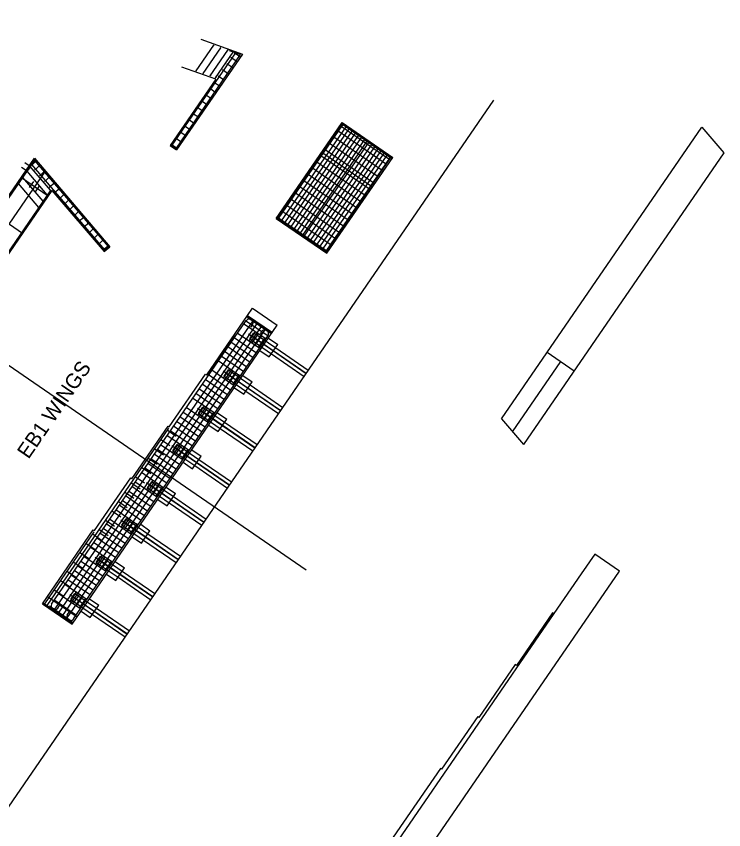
# Model space of a CAD drawing. Extents: x 2378999 to 2381348, y 331302 to 333122.
# Drawn here: x 2379415.6 to 2379509.6, y 331652.7 to 331760.8 of the extents above; entities that cross this region are included whole.
import ezdxf

# ---------------------------------------------------------------- set-up
doc = ezdxf.new("R2010")
doc.units = 0
for name, color, linetype in [('Arrowhead Terminators', 7, 'Continuous'), ('Dimension Lines', 7, 'Continuous'), ('Dimension Lines CELL', 7, 'Continuous'), ('Mis Work Point CELL', 7, 'Continuous'), ('P_SMU_Girder_Concrete', 7, 'Continuous'), ('P_SMU_Rebar_B_Bar', 7, 'Continuous'), ('P_SMU_Rebar_H_Bar', 7, 'Continuous'), ('P_SMU_Rebar_U_Bar', 7, 'Continuous'), ('P_SMU_Rebar_V_Bar', 7, 'Continuous'), ('Rebar Lines', 7, 'Continuous'), ('Scratch_Level_0', 7, 'Continuous'), ('Sup Concrete Slab Lines', 7, 'Continuous'), ('Text', 7, 'Continuous')]:
    doc.layers.add(name, color=color, linetype=linetype)

msp = doc.modelspace()

# ---------------------------------------------------------------- linework, layer by layer
at = {"layer": 'Arrowhead Terminators'}
for p, q in [((2379420.33, 331682.71), (2379446.2, 331720.36)), ((2379420.67, 331681.88), (2379447.1, 331720.34)), ((2379421.22, 331681.5), (2379447.65, 331719.97)), ((2379421.77, 331681.13), (2379448.2, 331719.59)), ((2379447.01, 331719.81), (2379446.77, 331719.47)), ((2379422.32, 331680.75), (2379448.75, 331719.21)), ((2379448.28, 331718.94), (2379448.04, 331718.59)), ((2379423.22, 331680.73), (2379449.09, 331718.38)), ((2379419.73, 331682.53), (2379435.92, 331706.08)), ((2379419.41, 331682.75), (2379425.97, 331692.29)), ((2379421.14, 331682.15), (2379421.37, 331682.5)), ((2379422.41, 331681.28), (2379422.64, 331681.62))]:
    msp.add_line(p, q, dxfattribs=at)
for centre, start, end in [((2379446.61, 331720.09), 325.5093, 145.5093), ((2379448.68, 331718.66), 325.5093, 145.5093), ((2379420.73, 331682.43), 145.5093, 325.5093), ((2379422.81, 331681), 145.5093, 325.5093)]:
    msp.add_arc(centre, 0.49, start, end, dxfattribs=at)
at = {"layer": 'Dimension Lines'}
for p, q in [((2379443.75, 331756.27), (2379443.8, 331756.43)), ((2379444.46, 331756.02), (2379444.51, 331756.18)), ((2379417.48, 331740.82), (2379416.76, 331741.31)), ((2379417.06, 331740.2), (2379416.34, 331740.69)), ((2379446.38, 331720.78), (2379449.37, 331718.72)), ((2379445.84, 331719.99), (2379448.83, 331717.94)), ((2379446.11, 331720.38), (2379449.1, 331718.33)), ((2379444.99, 331718.75), (2379447.98, 331716.7)), ((2379446.53, 331717.6), (2379447.47, 331718.97)), ((2379446.94, 331717.32), (2379447.88, 331718.69)), ((2379444.14, 331717.52), (2379447.13, 331715.46)), ((2379444.57, 331718.13), (2379447.56, 331716.08)), ((2379447.35, 331717.03), (2379448.29, 331718.41)), ((2379447.76, 331716.75), (2379448.71, 331718.12)), ((2379443.29, 331716.28), (2379446.28, 331714.23)), ((2379443.72, 331716.9), (2379446.71, 331714.85)), ((2379442.87, 331715.66), (2379445.86, 331713.61)), ((2379442.45, 331715.04), (2379445.43, 331712.99)), ((2379441.17, 331713.19), (2379444.16, 331711.14)), ((2379441.6, 331713.81), (2379444.58, 331711.75)), ((2379443.13, 331712.65), (2379444.07, 331714.03)), ((2379443.54, 331712.37), (2379444.48, 331713.74)), ((2379443.95, 331712.09), (2379444.9, 331713.46)), ((2379444.37, 331711.8), (2379445.31, 331713.18)), ((2379440.32, 331711.95), (2379443.31, 331709.9)), ((2379440.75, 331712.57), (2379443.73, 331710.52)), ((2379439.9, 331711.33), (2379442.89, 331709.28)), ((2379439.05, 331710.1), (2379442.04, 331708.05)), ((2379439.47, 331710.72), (2379442.46, 331708.66)), ((2379438.2, 331708.86), (2379441.19, 331706.81)), ((2379439.73, 331707.71), (2379440.67, 331709.08)), ((2379440.14, 331707.42), (2379441.09, 331708.8)), ((2379437.35, 331707.63), (2379440.34, 331705.57)), ((2379437.77, 331708.24), (2379440.76, 331706.19)), ((2379440.56, 331707.14), (2379441.5, 331708.52)), ((2379440.97, 331706.86), (2379441.91, 331708.23)), ((2379436.92, 331707.01), (2379439.91, 331704.95)), ((2379436.07, 331705.77), (2379439.06, 331703.72)), ((2379436.5, 331706.39), (2379439.49, 331704.34)), ((2379435.65, 331705.15), (2379438.64, 331703.1)), ((2379434.38, 331703.3), (2379437.36, 331701.25)), ((2379434.8, 331703.92), (2379437.79, 331701.86)), ((2379436.33, 331702.76), (2379437.28, 331704.14)), ((2379436.75, 331702.48), (2379437.69, 331703.85)), ((2379437.16, 331702.2), (2379438.1, 331703.57)), ((2379433.95, 331702.68), (2379436.94, 331700.63)), ((2379437.57, 331701.91), (2379438.51, 331703.29)), ((2379433.1, 331701.44), (2379436.09, 331699.39)), ((2379433.53, 331702.06), (2379436.51, 331700.01)), ((2379432.25, 331700.21), (2379435.24, 331698.16)), ((2379432.68, 331700.83), (2379435.67, 331698.77)), ((2379431.4, 331698.97), (2379434.39, 331696.92)), ((2379432.94, 331697.82), (2379433.88, 331699.19)), ((2379430.98, 331698.35), (2379433.97, 331696.3)), ((2379433.35, 331697.53), (2379434.29, 331698.91)), ((2379433.76, 331697.25), (2379434.7, 331698.62)), ((2379434.17, 331696.97), (2379435.12, 331698.34)), ((2379430.13, 331697.12), (2379433.12, 331695.06)), ((2379430.55, 331697.74), (2379433.54, 331695.68)), ((2379429.28, 331695.88), (2379432.27, 331693.83)), ((2379429.7, 331696.5), (2379432.69, 331694.45)), ((2379428.86, 331695.26), (2379431.84, 331693.21)), ((2379428.01, 331694.03), (2379430.99, 331691.97)), ((2379429.54, 331692.87), (2379430.48, 331694.25)), ((2379429.95, 331692.59), (2379430.89, 331693.96)), ((2379430.36, 331692.31), (2379431.31, 331693.68)), ((2379427.16, 331692.79), (2379430.14, 331690.74)), ((2379427.58, 331693.41), (2379430.57, 331691.36)), ((2379430.77, 331692.02), (2379431.72, 331693.4)), ((2379426.31, 331691.55), (2379429.29, 331689.5)), ((2379426.73, 331692.17), (2379429.72, 331690.12)), ((2379425.88, 331690.94), (2379428.87, 331688.88)), ((2379425.46, 331690.32), (2379428.45, 331688.26)), ((2379426.14, 331687.93), (2379427.08, 331689.3)), ((2379424.18, 331688.46), (2379427.17, 331686.41)), ((2379424.61, 331689.08), (2379427.6, 331687.03)), ((2379426.55, 331687.64), (2379427.5, 331689.02)), ((2379426.96, 331687.36), (2379427.91, 331688.73)), ((2379427.38, 331687.08), (2379428.32, 331688.45)), ((2379423.33, 331687.23), (2379426.32, 331685.17)), ((2379423.76, 331687.84), (2379426.75, 331685.79)), ((2379422.91, 331686.61), (2379425.9, 331684.56)), ((2379422.06, 331685.37), (2379425.05, 331683.32)), ((2379422.48, 331685.99), (2379425.47, 331683.94)), ((2379421.21, 331684.14), (2379424.2, 331682.08)), ((2379422.74, 331682.98), (2379423.69, 331684.36)), ((2379423.16, 331682.7), (2379424.1, 331684.07)), ((2379420.64, 331683.3), (2379423.62, 331681.25)), ((2379423.57, 331682.42), (2379424.51, 331683.79)), ((2379423.98, 331682.13), (2379424.92, 331683.51)), ((2379420.06, 331682.46), (2379423.05, 331680.41))]:
    msp.add_line(p, q, dxfattribs=at)
at = {"layer": 'Dimension Lines CELL'}
msp.add_line((2379454.16, 331687.23), (2379268.2, 331815), dxfattribs=at)
at = {"layer": 'Mis Work Point CELL'}
for p, q in [((2379402.05, 331637.52), (2379479.08, 331749.64)), ((2379392.88, 331701.47), (2379419.5, 331740.21))]:
    msp.add_line(p, q, dxfattribs=at)
at = {"layer": 'P_SMU_Girder_Concrete'}
for p, q in [((2379417.39, 331738.02), (2379417.96, 331738.84)), ((2379417.68, 331738.43), (2379418.49, 331737.87)), ((2379418.2, 331737.46), (2379418.77, 331738.29)), ((2379446.65, 331717.92), (2379447.21, 331718.74)), ((2379447.21, 331718.74), (2379450.1, 331716.76)), ((2379446.65, 331717.92), (2379449.53, 331715.94)), ((2379446.92, 331718.32), (2379454.15, 331713.35)), ((2379446.94, 331718.35), (2379454.17, 331713.38)), ((2379450.1, 331716.76), (2379454.44, 331713.78)), ((2379449.53, 331715.94), (2379453.88, 331712.95)), ((2379443.25, 331712.98), (2379443.82, 331713.8)), ((2379443.52, 331713.37), (2379450.75, 331708.41)), ((2379443.54, 331713.4), (2379450.77, 331708.44)), ((2379443.82, 331713.8), (2379446.7, 331711.82)), ((2379443.25, 331712.98), (2379446.13, 331710.99)), ((2379446.13, 331710.99), (2379450.48, 331708.01)), ((2379446.7, 331711.82), (2379451.05, 331708.83)), ((2379439.85, 331708.03), (2379440.42, 331708.85)), ((2379440.42, 331708.85), (2379443.3, 331706.87)), ((2379439.85, 331708.03), (2379442.74, 331706.05)), ((2379440.12, 331708.43), (2379447.35, 331703.46)), ((2379440.14, 331708.46), (2379447.37, 331703.49)), ((2379443.3, 331706.87), (2379447.65, 331703.89)), ((2379442.74, 331706.05), (2379447.08, 331703.06)), ((2379436.45, 331703.08), (2379437.02, 331703.91)), ((2379436.73, 331703.48), (2379443.96, 331698.51)), ((2379436.75, 331703.51), (2379443.98, 331698.54)), ((2379437.02, 331703.91), (2379439.9, 331701.93)), ((2379436.45, 331703.08), (2379439.34, 331701.1)), ((2379439.9, 331701.93), (2379444.25, 331698.94)), ((2379439.34, 331701.1), (2379443.68, 331698.12)), ((2379433.06, 331698.14), (2379433.62, 331698.96)), ((2379433.06, 331698.14), (2379435.94, 331696.16)), ((2379433.33, 331698.54), (2379440.56, 331693.57)), ((2379433.35, 331698.57), (2379440.58, 331693.6)), ((2379433.62, 331698.96), (2379436.51, 331696.98)), ((2379436.51, 331696.98), (2379440.85, 331694)), ((2379435.94, 331696.16), (2379440.29, 331693.17)), ((2379429.66, 331693.19), (2379430.22, 331694.02)), ((2379429.93, 331693.59), (2379437.16, 331688.62)), ((2379429.95, 331693.62), (2379437.18, 331688.65)), ((2379430.22, 331694.02), (2379433.11, 331692.04)), ((2379429.66, 331693.19), (2379432.54, 331691.21)), ((2379433.11, 331692.04), (2379437.45, 331689.05)), ((2379432.54, 331691.21), (2379436.89, 331688.23)), ((2379426.26, 331688.25), (2379426.83, 331689.07)), ((2379426.26, 331688.25), (2379429.15, 331686.27)), ((2379426.53, 331688.65), (2379433.76, 331683.68)), ((2379426.55, 331688.68), (2379433.78, 331683.71)), ((2379426.83, 331689.07), (2379429.71, 331687.09)), ((2379429.71, 331687.09), (2379434.06, 331684.11)), ((2379429.15, 331686.27), (2379433.49, 331683.28)), ((2379422.86, 331683.3), (2379423.43, 331684.13)), ((2379423.43, 331684.13), (2379426.31, 331682.15)), ((2379422.86, 331683.3), (2379425.75, 331681.32)), ((2379423.14, 331683.7), (2379430.37, 331678.73)), ((2379423.16, 331683.73), (2379430.39, 331678.76)), ((2379426.31, 331682.15), (2379430.66, 331679.16)), ((2379425.75, 331681.32), (2379430.09, 331678.34))]:
    msp.add_line(p, q, dxfattribs=at)
at = {"layer": 'P_SMU_Rebar_B_Bar'}
for p, q in [((2379440.16, 331757.72), (2379445.67, 331755.77)), ((2379445.67, 331755.77), (2379436.92, 331743.04)), ((2379442.15, 331752.42), (2379437.62, 331754.02)), ((2379442.15, 331752.42), (2379436.09, 331743.6)), ((2379450.18, 331733.92), (2379458.93, 331746.66)), ((2379458.93, 331746.66), (2379465.65, 331742.04)), ((2379480.12, 331707.3), (2379506.73, 331746.04)), ((2379506.73, 331746.04), (2379509.65, 331742.63)), ((2379436.09, 331743.6), (2379436.92, 331743.04)), ((2379453.6, 331731.57), (2379462.35, 331744.31)), ((2379456.24, 331742.74), (2379462.95, 331738.12)), ((2379509.65, 331742.63), (2379483.03, 331703.89)), ((2379391.43, 331703.18), (2379418.04, 331741.92)), ((2379418.04, 331741.92), (2379428.08, 331730.17)), ((2379456.9, 331729.31), (2379465.65, 331742.04)), ((2379420.37, 331737.65), (2379394.93, 331700.62)), ((2379420.37, 331737.65), (2379427.32, 331729.52)), ((2379450.18, 331733.92), (2379456.9, 331729.31)), ((2379427.32, 331729.52), (2379428.08, 331730.17)), ((2379446.37, 331721.05), (2379447.03, 331722)), ((2379447.03, 331722), (2379450.32, 331719.74)), ((2379440.94, 331713.14), (2379446.37, 331721.05)), ((2379446.37, 331721.05), (2379449.66, 331718.78)), ((2379423.05, 331680.04), (2379450.32, 331719.74)), ((2379449.14, 331718.02), (2379450.38, 331717.17)), ((2379448.01, 331716.38), (2379449.25, 331715.53)), ((2379449.25, 331715.53), (2379450.38, 331717.17)), ((2379486.2, 331716.16), (2379489.78, 331713.71)), ((2379435.96, 331706.25), (2379440.78, 331713.25)), ((2379440.78, 331713.25), (2379440.94, 331713.14)), ((2379445.75, 331713.08), (2379446.98, 331712.23)), ((2379445.85, 331710.58), (2379446.98, 331712.23)), ((2379444.61, 331711.43), (2379445.85, 331710.58)), ((2379442.35, 331708.13), (2379443.59, 331707.28)), ((2379442.45, 331705.64), (2379443.59, 331707.28)), ((2379480.12, 331707.3), (2379483.03, 331703.89)), ((2379430.99, 331699.35), (2379435.8, 331706.36)), ((2379435.8, 331706.36), (2379435.96, 331706.25)), ((2379441.22, 331706.49), (2379442.45, 331705.64)), ((2379438.95, 331703.19), (2379440.19, 331702.34)), ((2379439.06, 331700.69), (2379440.19, 331702.34)), ((2379437.82, 331701.54), (2379439.06, 331700.69)), ((2379426.02, 331692.46), (2379430.83, 331699.46)), ((2379430.83, 331699.46), (2379430.99, 331699.35)), ((2379435.55, 331698.24), (2379436.79, 331697.39)), ((2379435.66, 331695.75), (2379436.79, 331697.39)), ((2379434.42, 331696.59), (2379435.66, 331695.75)), ((2379419.11, 331682.75), (2379425.86, 331692.57)), ((2379425.86, 331692.57), (2379426.02, 331692.46)), ((2379432.16, 331693.3), (2379433.39, 331692.45)), ((2379431.02, 331691.65), (2379432.26, 331690.8)), ((2379432.26, 331690.8), (2379433.39, 331692.45)), ((2379428.76, 331688.35), (2379429.99, 331687.5)), ((2379428.86, 331685.85), (2379429.99, 331687.5)), ((2379427.63, 331686.7), (2379428.86, 331685.85)), ((2379419.77, 331683.71), (2379423.71, 331681)), ((2379425.36, 331683.41), (2379426.6, 331682.56)), ((2379419.11, 331682.75), (2379423.05, 331680.04)), ((2379424.23, 331681.76), (2379425.46, 331680.91)), ((2379425.46, 331680.91), (2379426.6, 331682.56)), ((2379486.91, 331681.56), (2379487.07, 331681.45))]:
    msp.add_line(p, q, dxfattribs=at)
at = {"layer": 'P_SMU_Rebar_H_Bar'}
for p, q in [((2379444.75, 331755.92), (2379436.32, 331743.65)), ((2379445.4, 331755.69), (2379436.87, 331743.27)), ((2379444.75, 331755.92), (2379443.97, 331756.19)), ((2379445.4, 331755.69), (2379444.62, 331755.96)), ((2379450.48, 331733.92), (2379459.04, 331746.38)), ((2379450.89, 331733.63), (2379459.45, 331746.1)), ((2379451.31, 331733.35), (2379459.87, 331745.81)), ((2379451.72, 331733.07), (2379460.28, 331745.53)), ((2379452.13, 331732.79), (2379460.69, 331745.25)), ((2379452.54, 331732.5), (2379461.1, 331744.96)), ((2379452.95, 331732.22), (2379461.51, 331744.68)), ((2379453.37, 331731.94), (2379461.93, 331744.4)), ((2379453.9, 331731.57), (2379462.46, 331744.03)), ((2379454.31, 331731.29), (2379462.87, 331743.75)), ((2379454.72, 331731), (2379463.29, 331743.46)), ((2379455.14, 331730.72), (2379463.7, 331743.18)), ((2379455.55, 331730.44), (2379464.11, 331742.9)), ((2379455.96, 331730.15), (2379464.52, 331742.61)), ((2379456.37, 331729.87), (2379464.93, 331742.33)), ((2379418.05, 331741.64), (2379417.58, 331740.96)), ((2379418.05, 331741.64), (2379427.84, 331730.19)), ((2379456.79, 331729.59), (2379465.35, 331742.05)), ((2379417.66, 331741.08), (2379417.19, 331740.39)), ((2379417.66, 331741.08), (2379427.34, 331729.76))]:
    msp.add_line(p, q, dxfattribs=at)
at = {"layer": 'P_SMU_Rebar_U_Bar'}
for p, q in [((2379439.52, 331753.53), (2379441.86, 331756.94)), ((2379440.46, 331753.19), (2379442.81, 331756.61)), ((2379441.4, 331752.86), (2379443.75, 331756.27)), ((2379442.11, 331752.61), (2379444.46, 331756.02)), ((2379419.75, 331737.05), (2379417.06, 331740.2)), ((2379420.17, 331737.67), (2379417.48, 331740.82)), ((2379419.18, 331736.22), (2379416.49, 331739.37)), ((2379418.62, 331735.4), (2379415.93, 331738.55)), ((2379435.66, 331705.85), (2379436.89, 331705)), ((2379434.81, 331704.62), (2379436.05, 331703.77)), ((2379433.96, 331703.38), (2379435.2, 331702.53)), ((2379433.11, 331702.14), (2379434.35, 331701.29)), ((2379432.26, 331700.91), (2379433.5, 331700.06)), ((2379431.41, 331699.67), (2379432.65, 331698.82)), ((2379430.85, 331698.85), (2379432.08, 331698)), ((2379430, 331697.61), (2379431.23, 331696.76)), ((2379429.15, 331696.37), (2379430.38, 331695.52)), ((2379428.3, 331695.14), (2379429.53, 331694.29)), ((2379427.45, 331693.9), (2379428.68, 331693.05)), ((2379426.6, 331692.66), (2379427.83, 331691.82)), ((2379425.71, 331692.06), (2379426.95, 331691.21)), ((2379424.86, 331690.82), (2379426.1, 331689.97)), ((2379424.01, 331689.59), (2379425.25, 331688.74)), ((2379423.16, 331688.35), (2379424.4, 331687.5)), ((2379422.31, 331687.12), (2379423.55, 331686.27)), ((2379421.46, 331685.88), (2379422.7, 331685.03)), ((2379420.61, 331684.64), (2379421.85, 331683.79))]:
    msp.add_line(p, q, dxfattribs=at)
at = {"layer": 'P_SMU_Rebar_V_Bar'}
for p, q in [((2379458.39, 331745.57), (2379464.83, 331741.15)), ((2379458.81, 331746.19), (2379465.25, 331741.77)), ((2379457.82, 331744.75), (2379464.26, 331740.32)), ((2379457.26, 331743.92), (2379463.7, 331739.5)), ((2379456.12, 331742.28), (2379462.56, 331737.85)), ((2379456.69, 331743.1), (2379463.13, 331738.68)), ((2379455.56, 331741.45), (2379462, 331737.03)), ((2379454.99, 331740.63), (2379461.43, 331736.2)), ((2379453.86, 331738.98), (2379460.3, 331734.55)), ((2379454.42, 331739.8), (2379460.86, 331735.38)), ((2379453.29, 331738.15), (2379459.73, 331733.73)), ((2379452.72, 331737.33), (2379459.17, 331732.91)), ((2379452.16, 331736.51), (2379458.6, 331732.08)), ((2379451.03, 331734.86), (2379457.47, 331730.43)), ((2379451.59, 331735.68), (2379458.03, 331731.26)), ((2379450.46, 331734.03), (2379456.9, 331729.61))]:
    msp.add_line(p, q, dxfattribs=at)
for centre in [(2379441.85, 331756.92), (2379442.79, 331756.59), (2379443.74, 331756.26), (2379444.44, 331756), (2379445.26, 331755.51), (2379444.26, 331754.06), (2379444.83, 331754.89), (2379439.53, 331753.54), (2379440.47, 331753.21), (2379443.7, 331753.24), (2379441.42, 331752.88), (2379442.05, 331751.94), (2379442.12, 331752.63), (2379443.13, 331752.41), (2379441.48, 331751.12), (2379442.57, 331751.59), (2379440.92, 331750.3), (2379441.43, 331749.94), (2379442, 331750.77), (2379440.35, 331749.47), (2379440.87, 331749.12), (2379439.22, 331747.82), (2379439.79, 331748.65), (2379440.3, 331748.29), (2379438.65, 331747), (2379439.17, 331746.64), (2379439.73, 331747.47), (2379438.09, 331746.17), (2379438.6, 331745.82), (2379436.95, 331744.53), (2379437.52, 331745.35), (2379438.04, 331745), (2379436.39, 331743.7), (2379436.9, 331743.35), (2379437.47, 331744.17), (2379418.19, 331741.45), (2379417.07, 331740.18), (2379417.5, 331740.8), (2379418.68, 331740.88), (2379419.33, 331740.12), (2379416.51, 331739.36), (2379419.98, 331739.36), (2379415.94, 331738.53), (2379420.63, 331738.6), (2379419.74, 331737.06), (2379420.16, 331737.68), (2379420.8, 331737.44), (2379421.28, 331737.84), (2379421.93, 331737.08), (2379419.17, 331736.24), (2379421.45, 331736.68), (2379422.1, 331735.92), (2379422.58, 331736.32), (2379418.6, 331735.42), (2379422.75, 331735.16), (2379423.23, 331735.56), (2379423.87, 331734.8), (2379423.4, 331734.39), (2379424.05, 331733.63), (2379424.52, 331734.04), (2379424.7, 331732.87), (2379425.17, 331733.28), (2379425.82, 331732.52), (2379425.35, 331732.11), (2379426.47, 331731.76), (2379426, 331731.35), (2379426.65, 331730.59), (2379427.12, 331731), (2379427.3, 331729.83), (2379427.77, 331730.24)]:
    msp.add_circle(centre, 0.0208, dxfattribs=at)
at = {"layer": 'Rebar Lines'}
for p, q in [((2379416.3, 331739.38), (2379419.87, 331736.93)), ((2379412.9, 331734.43), (2379416.47, 331731.98)), ((2379446.51, 331718.62), (2379454.16, 331713.37)), ((2379443.11, 331713.68), (2379450.76, 331708.42)), ((2379439.71, 331708.73), (2379447.36, 331703.47)), ((2379436.32, 331703.78), (2379443.97, 331698.53)), ((2379432.92, 331698.84), (2379440.57, 331693.58)), ((2379429.52, 331693.89), (2379437.17, 331688.64)), ((2379426.12, 331688.95), (2379433.77, 331683.69)), ((2379422.73, 331684), (2379430.38, 331678.75))]:
    msp.add_line(p, q, dxfattribs=at)
at = {"layer": 'Scratch_Level_0'}
for p, q in [((2379444.16, 331755.35), (2379444.99, 331754.78)), ((2379444.59, 331755.97), (2379445.41, 331755.4)), ((2379443.59, 331754.52), (2379444.42, 331753.96)), ((2379443.03, 331753.7), (2379443.85, 331753.13)), ((2379441.9, 331752.05), (2379442.72, 331751.48)), ((2379442.46, 331752.87), (2379443.29, 331752.31)), ((2379441.33, 331751.23), (2379442.15, 331750.66)), ((2379440.76, 331750.4), (2379441.59, 331749.84)), ((2379439.63, 331748.75), (2379440.46, 331748.19)), ((2379440.2, 331749.58), (2379441.02, 331749.01)), ((2379439.06, 331747.93), (2379439.89, 331747.36)), ((2379438.5, 331747.11), (2379439.32, 331746.54)), ((2379450.32, 331733.83), (2379459.07, 331746.56)), ((2379458.84, 331746.52), (2379465.55, 331741.91)), ((2379437.37, 331745.46), (2379438.19, 331744.89)), ((2379437.93, 331746.28), (2379438.76, 331745.71)), ((2379436.8, 331744.63), (2379437.62, 331744.07)), ((2379436.19, 331743.74), (2379437.01, 331743.17)), ((2379436.23, 331743.81), (2379437.06, 331743.24)), ((2379391.56, 331703.09), (2379418.18, 331741.82)), ((2379417.57, 331740.93), (2379418.33, 331741.58)), ((2379456.76, 331729.4), (2379465.51, 331742.14)), ((2379418.06, 331740.36), (2379418.82, 331741.01)), ((2379418.71, 331739.6), (2379419.47, 331740.24)), ((2379419.36, 331738.83), (2379420.12, 331739.48)), ((2379420.01, 331738.07), (2379420.77, 331738.72)), ((2379420.66, 331737.31), (2379421.42, 331737.96)), ((2379420.23, 331737.75), (2379394.79, 331700.72)), ((2379421.31, 331736.55), (2379422.07, 331737.2)), ((2379421.96, 331735.79), (2379422.72, 331736.44)), ((2379422.61, 331735.03), (2379423.37, 331735.68)), ((2379423.26, 331734.27), (2379424.02, 331734.92)), ((2379423.91, 331733.51), (2379424.67, 331734.16)), ((2379450.28, 331734.06), (2379456.99, 331729.45)), ((2379424.56, 331732.75), (2379425.32, 331733.4)), ((2379425.21, 331731.99), (2379425.97, 331732.64)), ((2379425.86, 331731.23), (2379426.62, 331731.88)), ((2379426.5, 331730.47), (2379427.27, 331731.12)), ((2379427.15, 331729.71), (2379427.91, 331730.36)), ((2379427.21, 331729.65), (2379427.97, 331730.3)), ((2379446.27, 331720.91), (2379449.57, 331718.64)), ((2379441.08, 331713.05), (2379444.7, 331718.32)), ((2379419.21, 331682.89), (2379423.14, 331680.18))]:
    msp.add_line(p, q, dxfattribs=at)
at = {"layer": 'Text'}
for p, q in [((2379481.57, 331705.6), (2379487.99, 331714.94)), ((2379487.07, 331681.45), (2379465.88, 331650.62))]:
    msp.add_line(p, q, dxfattribs=at)
msp.add_lwpolyline([(2379467.1, 331653.76), (2379465.24, 331651.06), (2379469.18, 331648.35), (2379495.8, 331687.09), (2379492.5, 331689.35), (2379490.69, 331686.72), (2379487.07, 331681.45), (2379486.91, 331681.56), (2379482.09, 331674.56), (2379481.93, 331674.66), (2379477.12, 331667.66), (2379476.96, 331667.77), (2379472.15, 331660.76), (2379471.99, 331660.87)], close=True, dxfattribs=at)

# ---------------------------------------------------------------- texts
at = {"layer": 'Sup Concrete Slab Lines'}
msp.add_text('EB1 WINGS', height=2, rotation=55.5093, dxfattribs=at).set_placement((2379417.25, 331701.87))

doc.saveas('drawing.dxf')
